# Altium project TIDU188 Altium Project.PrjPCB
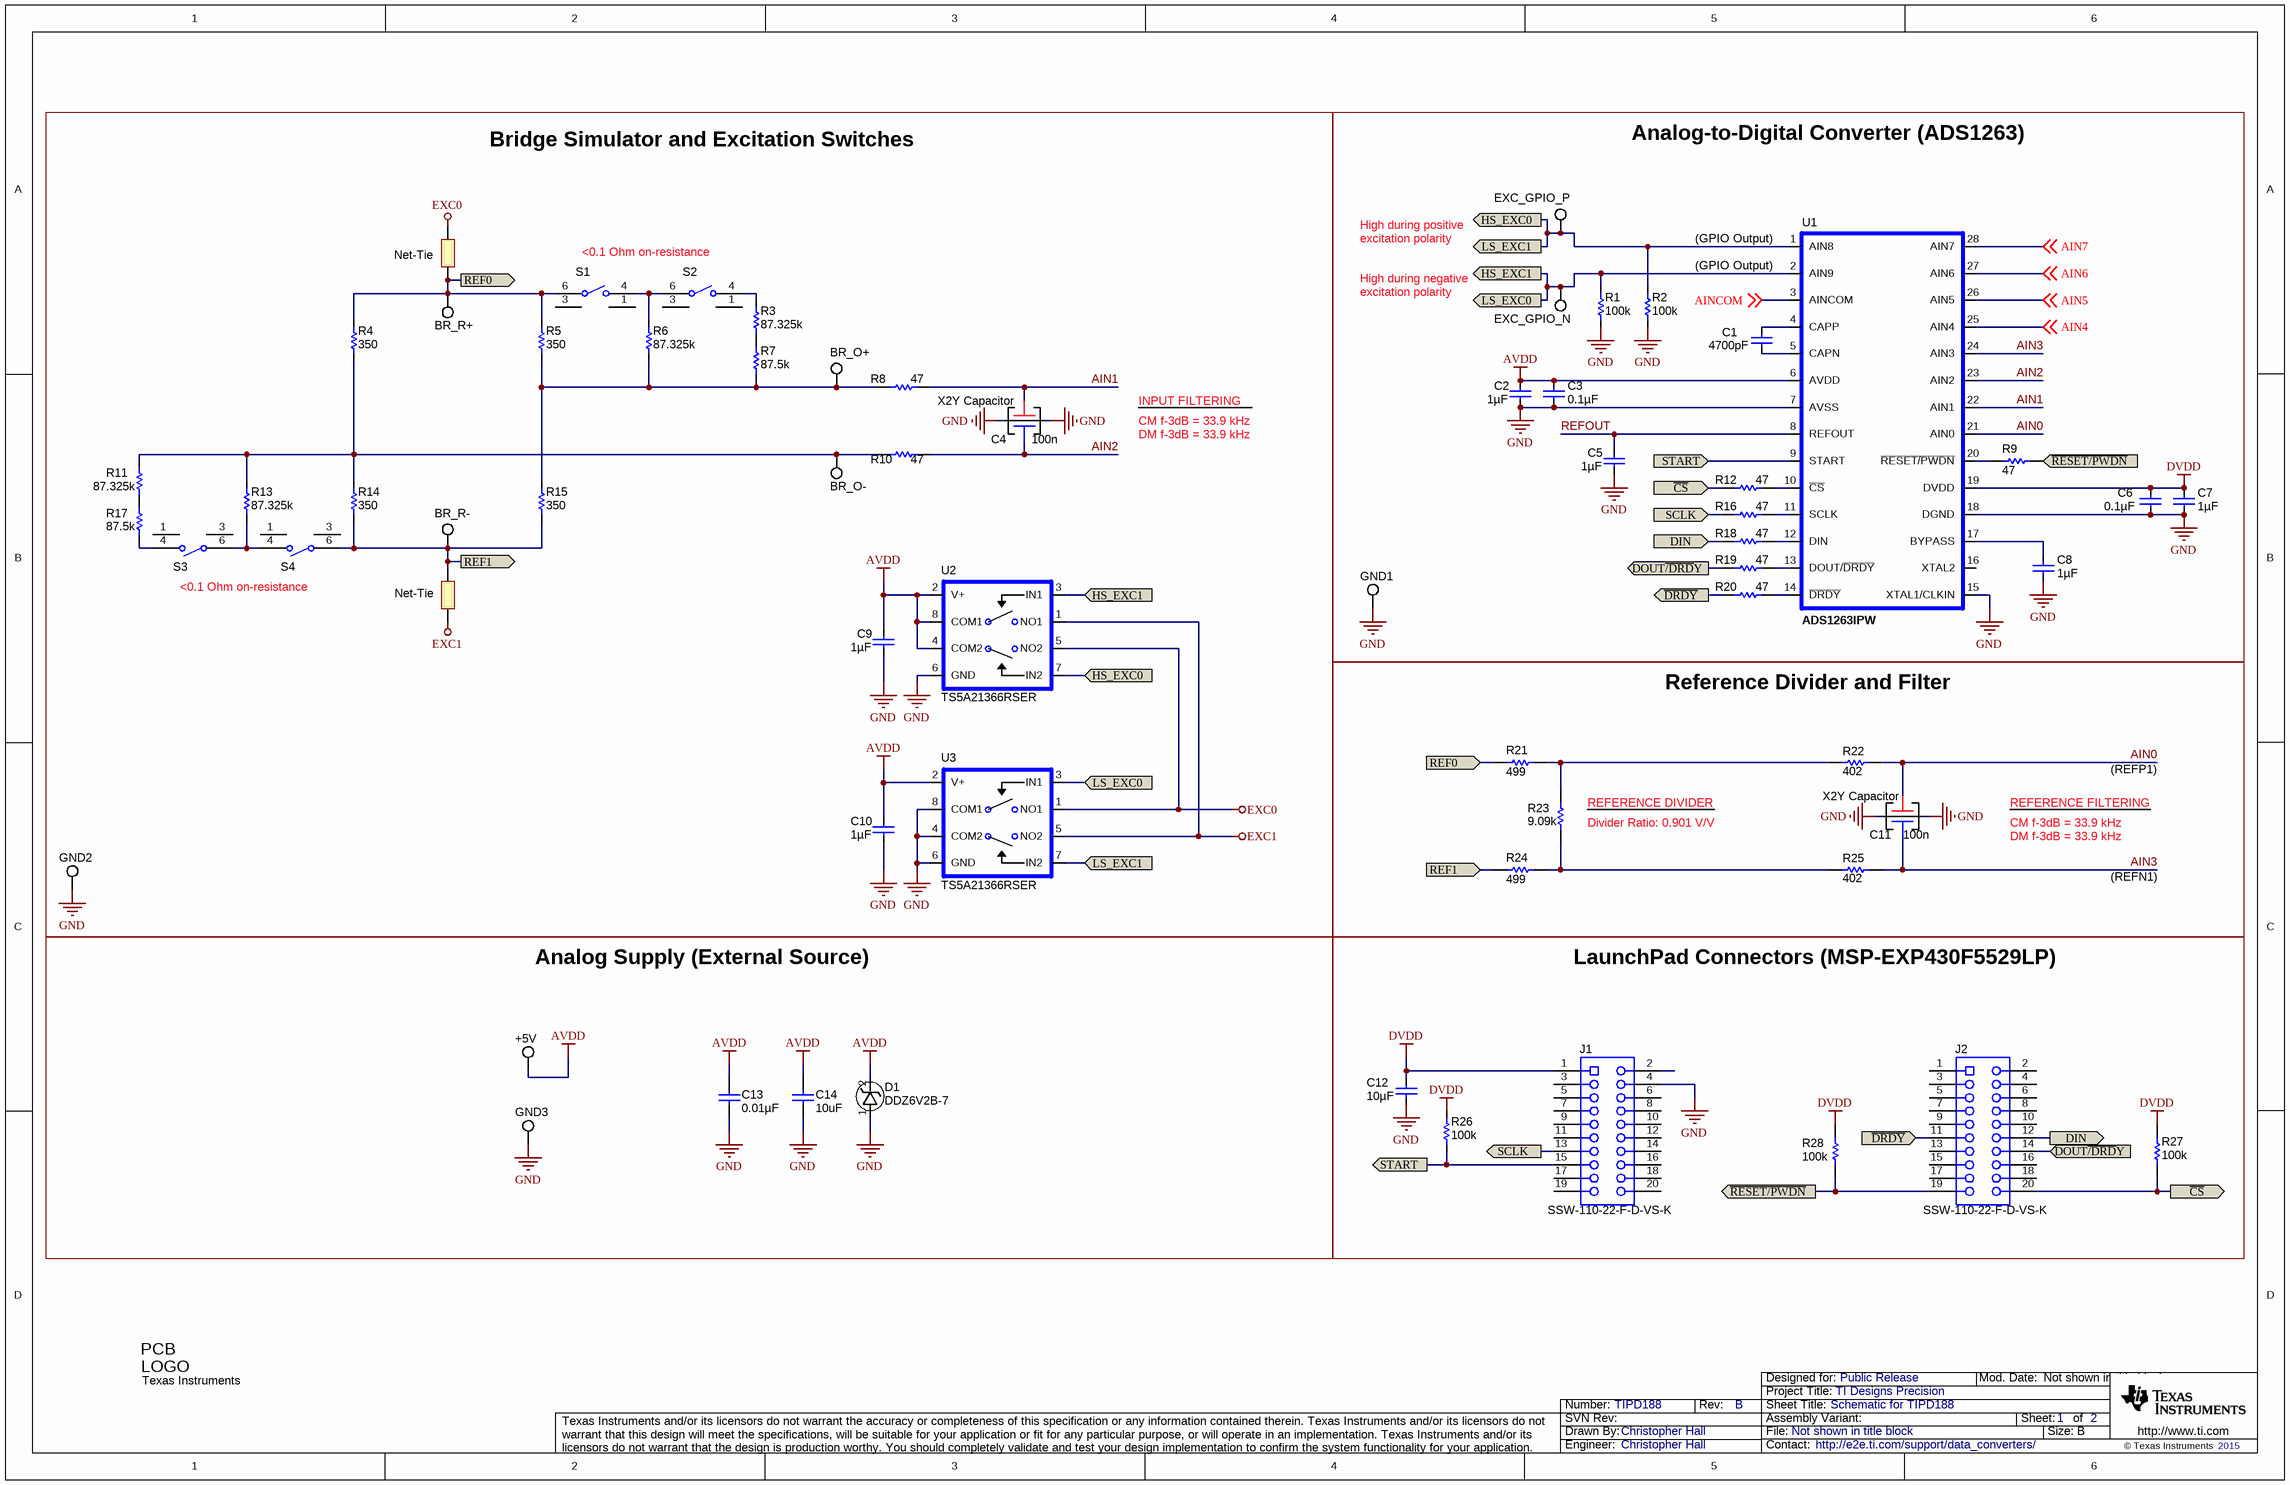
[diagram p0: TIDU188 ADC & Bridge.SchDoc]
CopyrightYear: 2015; EVM_Orderable: N/A; PCB_Layout: Robert Hoof; PCB_Rev: B; PRJ_Customer: Public Release; PRJ_Engineer: Christopher Hall; PRJ_Number: TIPD188; PRJ_Title: TI Designs Precision; SCH_Rev: B; TechSupport: http://e2e.ti.com/support/data_converters/; TID: TIPD188
2 sheets, 74 parts. Net scope: flat (ports and power ports of the same name join across sheets).
Board file: TIDU188 PCB Layout.PcbDoc
Sheets:
  TIDU188 ADC & Bridge.SchDoc
  TIDU188 Temp Sensor.SchDoc

## Sheet TIDU188 ADC & Bridge.SchDoc: Schematic for TIPD188
size 431 x 279 mm; Date: Not shown in title block; ApprovedBy: Not shown in title block; CheckedBy: Not shown in title block; Author: Not shown in title block; CompanyName: Not shown in title block; DrawnBy: Christopher Hall; Engineer: Not shown in title block; Organization: Not shown in title block; Address1: Not shown in title block; Address2: Not shown in title block; Address3: Not shown in title block; Address4: Not shown in title block; DocumentNumber: 1; Revision: Use project parameter SCH_Rev; SheetNumber: 1; SheetTotal: 2; PageSetup: Record=PageOptions¦CenterHorizontal=True¦CenterVertical=True¦PrintScale=1.00¦XCorrection=1.00¦YCorrection=1.00¦PrintKind=0¦BorderSize=5000000¦LeftOffset=0¦BottomOffset=0¦Orientation=2¦PaperLength=1000¦PaperWidth=1000¦Scale=100¦PaperSource=15¦PrintQuality=600¦MediaType=1¦DitherType=10¦PaperKind=Letter¦PrintScaleMode=1

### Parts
+5V  5015  [5015]  (value not drawn)
BR_O+  5015  [5015]  (value not drawn)
BR_O-  5015  [5015]  (value not drawn)
BR_R+  5015  [5015]  (value not drawn)
BR_R-  5015  [5015]  (value not drawn)
C1  value 4700pF  [0603]  (hidden comment: GRM188R71H472KA01D)
C2  value 1µF  [0603]  (hidden comment: GRM185R61C105KE44D)
C3  value 0.1µF  [0603]  (hidden comment: GRM188R71C104KA01D)
C4  value 100n  [X2Y 0805 (X15)]  (hidden comment: 250X15W104MV4E)
C5  value 1µF  [0603]  (hidden comment: GRM185R61C105KE44D)
C6  value 0.1µF  [0603]  (hidden comment: GRM188R71C104KA01D)
C7  value 1µF  [0603]  (hidden comment: GRM185R61C105KE44D)
C8  value 1µF  [0603]  (hidden comment: GRM185R61C105KE44D)
C9  value 1µF  [0603]  (hidden comment: GRM185R61C105KE44D)
C10  value 1µF  [0603]  (hidden comment: GRM185R61C105KE44D)
C11  value 100n  [X2Y 0805 (X15)]  (hidden comment: 250X15W104MV4E)
C12  value 10µF  [1206]  (hidden comment: C3216X7R1C106M)
C13  ValueDisplayed: 0.01µF  [0603]  (hidden comment: GRM188R71E103KA01D)
C14  value 10uF  [1206]  (hidden comment: C3216X7R1C106M)
D1  DDZ6V2B-7  [SOD-123]
EXC_GPIO_N  5015  [5015]  (value not drawn)
EXC_GPIO_P  5015  [5015]  (value not drawn)
GND1  5015  [5015]  (value not drawn)
GND2  5015  [5015]  (value not drawn)
GND3  5015  [5015]  (value not drawn)
J1  SSW-110-22-F-D-VS-K  [CONN_SSW-110-22-F-D-VS-K]
J2  SSW-110-22-F-D-VS-K  [CONN_SSW-110-22-F-D-VS-K]
Logo1  Texas Instruments  [TI_Horizontal_Overlay_Small]  (no BOM)
NT1  Net-Tie  [Net-Tie_10mil]  (net tie, no BOM)
NT2  Net-Tie  [Net-Tie_10mil]  (net tie, no BOM)
R1  value 100k  [0603]  (hidden comment: ERJ-3GEYJ104V)
R2  value 100k  [0603]  (hidden comment: ERJ-3GEYJ104V)
R3  value 87.325k  [2512]  (hidden comment: 804-2512)
R4  value 350  [1206]  (hidden comment: 804-1206)
R5  value 350  [1206]  (hidden comment: 804-1206)
R6  value 87.325k  [2512]  (hidden comment: 804-2512)
R7  value 87.5k  [2512]  (hidden comment: 804-2512)
R8  value 47  [0805_HV]  (hidden comment: ERJ-3EKF47R0V)
R9  value 47  [0603]  (hidden comment: ERJ-3EKF47R0V)
R10  value 47  [0805_HV]  (hidden comment: ERJ-3EKF47R0V)
R11  value 87.325k  [2512]  (hidden comment: 804-2512)
R12  value 47  [0603]  (hidden comment: ERJ-3EKF47R0V)
R13  value 87.325k  [2512]  (hidden comment: 804-2512)
R14  value 350  [1206]  (hidden comment: 804-1206)
R15  value 350  [1206]  (hidden comment: 804-1206)
R16  value 47  [0603]  (hidden comment: ERJ-3EKF47R0V)
R17  value 87.5k  [2512]  (hidden comment: 804-2512)
R18  value 47  [0603]  (hidden comment: ERJ-3EKF47R0V)
R19  value 47  [0603]  (hidden comment: ERJ-3EKF47R0V)
R20  value 47  [0603]  (hidden comment: ERJ-3EKF47R0V)
R21  value 499  [0603]  (hidden comment: RG1608P-4990-B-T5)
R22  value 402  [0805_HV]  (hidden comment: 2-1879336-4)
R23  value 9.09k  [0603]  (hidden comment: RG1608P-9091-B-T5)
R24  value 499  [0603]  (hidden comment: RG1608P-4990-B-T5)
R25  value 402  [0805_HV]  (hidden comment: 2-1879336-4)
R26  value 100k  [0603]  (hidden comment: ERJ-3GEYJ104V)
R27  value 100k  [0603]  (hidden comment: ERJ-3GEYJ104V)
R28  value 100k  [0603]  (hidden comment: ERJ-3GEYJ104V)
S1  200USP9T1A1M2RE  [200USP9xxxxM2]  (value not drawn)
S2  200USP9T1A1M2RE  [200USP9xxxxM2]  (value not drawn)
S3  200USP9T1A1M2RE  [200USP9xxxxM2]  (value not drawn)
S4  200USP9T1A1M2RE  [200USP9xxxxM2]  (value not drawn)
U1  ADS1263IPW  [PW28]
U2  TS5A21366RSER  [RSE-8]
U3  TS5A21366RSER  [RSE-8]

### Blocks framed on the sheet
Bridge Simulator and Excitation Switches: BR_O+ BR_O- BR_R+ BR_R- C4 C9 C10 GND2 NT1 NT2 R3-R8 R10 R11 R13-R15 R17 S1-S4 U2 U3
Analog-to-Digital Converter (ADS1263): C1-C3 C5-C8 EXC_GPIO_N EXC_GPIO_P GND1 R1 R2 R9 R12 R16 R18-R20 U1
Reference Divider and Filter: C11 R21-R25
Analog Supply (External Source): +5V C13 C14 D1 GND3
LaunchPad Connectors (MSP-EXP430F5529LP): C12 J1 J2 R26-R28

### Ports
DIN (in), DIN (out), DOUT~{/DRD}Y (in), DOUT~{/DRD}Y (out), HS_EXC0, HS_EXC1, LS_EXC0, LS_EXC1, REF0 (in), REF0 (out), REF1 (in), REF1 (out), SCLK (in), SCLK (out), START (in), START (out), ~{CS} (in), ~{CS} (out), ~{DRDY} (in), ~{DRDY} (out), ~{RESET/PWDN} (in), ~{RESET/PWDN} (out)

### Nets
AVDD: +5V.1 C2.1 C3.1 C9.2 C10.2 C13.1 C14.1 D1.2(Cathode) U1.6(AVDD) U2.2(V+) U2.4(COM2) U2.8(COM1) U3.2(V+)
DVDD: C6.1 C7.1 C12.1 J1.1 R26.1 R27.1 R28.2 U1.19(DVDD)
EXC0: NT1.2 U2.5(NO2) U3.1(NO1)
EXC1: NT2.1 U2.1(NO1) U3.5(NO2)
GND: C2.2 C3.2 C4.G C5.2 C6.2 C7.2 C8.2 C9.1 C10.1 C11.G C12.2 C13.2 C14.2 D1.1(Anode) GND1.1 GND2.1 GND3.1 J1.4 R1.2 R2.2 U1.7(AVSS) U1.15(XTAL1/CLKIN) U1.18(DGND) U2.6(GND) U3.4(COM2) U3.6(GND) U3.8(COM1)
~{CS}: J2.20 R12.2 R27.2 ; port ~{CS}
~{DRDY}: J2.11 R20.2 ; port ~{DRDY}
~{RESET/PWDN}: J2.19 R9.2 R28.1 ; port ~{RESET/PWDN}
AIN0: C11.A R22.2 U1.21(AIN0)
AIN1: C4.A R8.2 U1.22(AIN1)
AIN2: C4.B R10.2 U1.23(AIN2)
AIN3: C11.B R25.2 U1.24(AIN3)
AIN4: U1.25(AIN4) ; off-sheet AIN4
AIN5: U1.26(AIN5) ; off-sheet AIN5
AIN6: U1.27(AIN6) ; off-sheet AIN6
AIN7: U1.28(AIN7) ; off-sheet AIN7
AINCOM: U1.3(AINCOM) ; off-sheet AINCOM
DIN: J2.12 R18.2 ; port DIN
DOUT~{/DRD}Y: J2.14 R19.2 ; port DOUT~{/DRD}Y
HS_EXC0: EXC_GPIO_P.1 R2.1 U1.1(AIN8) U2.7(IN2) U3.7(IN2) ; port HS_EXC0, port LS_EXC1
HS_EXC1: EXC_GPIO_N.1 R1.1 U1.2(AIN9) U2.3(IN1) U3.3(IN1) ; port HS_EXC1, port LS_EXC0
REF0: BR_R+.1 NT1.1 R4.2 R5.2 R21.1 S1.6 ; port REF0
REF1: BR_R-.1 NT2.2 R14.1 R15.1 R24.1 S4.6 ; port REF1
REFOUT: C5.1 U1.8(REFOUT)
SCLK: J1.13 R16.2 ; port SCLK
START: J1.15 R26.2 U1.9(START) ; port START
NetBR_O+_1: BR_O+.1 R5.1 R6.1 R7.1 R8.1 R15.2
NetBR_O-_1: BR_O-.1 R4.1 R10.1 R11.2 R13.2 R14.2
NetC1_1: C1.1 U1.4(CAPP)
NetC1_2: C1.2 U1.5(CAPN)
NetC8_1: C8.1 U1.17(BYPASS)
NetR3_1: R3.1 R7.2
NetR3_2: R3.2 S2.4
NetR6_2: R6.2 S1.4 S2.6
NetR9_1: R9.1 U1.20(~{RESET/PWDN})
NetR11_1: R11.1 R17.2
NetR12_1: R12.1 U1.10(~{CS})
NetR13_1: R13.1 S3.6 S4.4
NetR16_1: R16.1 U1.11(SCLK)
NetR17_1: R17.1 S3.4
NetR18_1: R18.1 U1.12(DIN)
NetR19_1: R19.1 U1.13(DOUT/~{DRDY})
NetR20_1: R20.1 U1.14(~{DRDY})
NetR21_2: R21.2 R22.1 R23.2
NetR23_1: R23.1 R24.2 R25.1

Not connected (* = marked no-connect by the designer): J1 2 3 5 6 7 8 9 10 11 12 14 16 17 18 19 20; J2 1 2 3 4 5 6 7 8 9 10 13 15 16 17 18; S1 1 3; S2 1 3; S3 1 3; S4 1 3; U1 16(XTAL2)

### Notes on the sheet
- High during positive
- <0.1 Ohm on-resistance
- excitation polarity
- High during negative
- (near U1) (GPIO Output)
- (near C4) X2Y Capacitor
- CM f-3dB = 33.9 kHz
- DM f-3dB = 33.9 kHz
- INPUT FILTERING
- (REFP1)
- (near R23) Divider Ratio: 0.901 V/V
- (near R23) REFERENCE DIVIDER
- (near C11) X2Y Capacitor
- REFERENCE FILTERING
- (REFN1)

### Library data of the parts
+5V BR_O+ BR_O- BR_R+ BR_R- EXC_GPIO_N EXC_GPIO_P GND1-GND3 = Test Point SMT: TEST POINT, MINIATURE, SMT; Manufacturer: Keystone Electronics; SymbolCreator: a0282860; U/M: EA
C1 = Cap_small: CAP, CERM, 4700pF, 50V, +/-10%, X7R, 0603; Manufacturer: MuRata; SymbolCreator: a0282860; CompType: Capacitor; U/M: EA
C2 C5 C7-C10 = Cap_small: CAP, CERM, 1uF, 16V, +/-10%, X5R, 0603; Manufacturer: MuRata; SymbolCreator: a0282860; CompType: Capacitor; U/M: EA
C3 C6 = Cap_small: CAP, CERM, 0.1uF, 16V, +/-10%, X7R, 0603; Manufacturer: MuRata; SymbolCreator: a0282860; CompType: Capacitor; U/M: EA
C4 C11 = CAP_X2Y: CAP, CERM X2Y, 100 nF, 25V, X7R, +/-20%, 0805; Manufacturer: Johanson Dielectrics Inc; SymbolCreator: a0282860; U/M: EA; CompType: X2Y Capacitor
C12 = Cap_small: CAP, CERM, 10 uF, 16V, X7R +/-20%, 1206; Manufacturer: TDK; PartNumber: C3216X7R1C106M160AC; SymbolCreator: a0282860; CompType: Capacitor; U/M: EA
C13 = GRM188R71E103KA01D: CAP, CERM, 0.01uF, 25V, +/-10%, X7R, 0603; Manufacturer: MuRata; Polarized: N; CompType: Capacitor; U/M: EA; Cap_F: 0.00000001; Tolerance_%: 10; Value1: Unknown; VDC_V: 25; TaMin_C: -55; TaMax_C: 125
C14 = Capacitor: CAP, CERM, 10 uF, 16V,  X7R +/-20%, 1206; Manufacturer: TDK; Polarized: N; U/M: EA; SymbolCreator: a0282860; Tolerance: 20%
D1 = Zener Diode: DIODE, ZENER, 6.2V, 500mW, SOD-123; Manufacturer: Diodes Inc; SymbolCreator: a0282860; U/M: EA
J1 J2 = SSW-110-22-F-D-VS-K: Connector, Receptacle, 100mil, 10x2, Gold plated, SMD; Manufacturer: Samtec; SymbolCreator: a0412235; U/M: EA
Logo1 = TI_Logo: Texas Instrument Corporate Signature; SymbolCreator: a0412235
NT1 NT2 = Net-Tie: Single point connection between nets.; SymbolCreator: codlsc
R1 R2 R26 = Resistor_small: RES, 100k Ohm, 5%, 1/10W, 0603; Manufacturer: Panasonic; U/M: EA
R3 R6 R11 R13 = Resistor_small: RES, 87.325k Ohm, 0.01%, 0.75W, 2512; Manufacturer: Vishay; U/M: EA
R4 R5 R14 R15 = Resistor_small: RES, 350 Ohm, 0.25%, 0.3W, 1206; Manufacturer: Vishay; U/M: EA
R7 = Resistor_small: RES, 87.5 kohm, 0.5%, 0.75W, 2512; Manufacturer: Vishay; U/M: EA
R8-R10 R12 R16 R18-R20 = Resistor: RES, 47 Ohm, 1%, 1/10W, 0603; Manufacturer: Panasonic; U/M: EA; SymbolCreator: a0282860
R17 = Resistor_small: RES, 87.5k Ohm, 0.5%, 0.75W, 2512; Manufacturer: Vishay; U/M: EA
R21 R24 = RG1608P-4990-B-T5: RES, 499 ohm, 0.1%, 0.1W, 0603; Manufacturer: Susumu Co Ltd; CompType: Resistor; Value_Code: 499R; Tolerance_%: 0.1; VDC_V: 75; TempCo: 25 ppm/C; EIA_Code: E192; U/M: EA
R22 R25 = Resistor: RES, 47 Ohm, 1%, 1/10W, 0603; Manufacturer: TE Connectivity AMP Connectors; Power_W: 0.063W, 1/16W; TempCo: ±50ppm/°C
R23 = RG1608P-9091-B-T5: RES, 9.09k ohm, 0.1%, 0.1W, 0603; Manufacturer: Susumu Co Ltd; CompType: Resistor; Res_ohm: 9090; Value_Code: 9k09; Tolerance_%: 0.1; VDC_V: 75; TempCo: 25 ppm/C; EIA_Code: E192; U/M: EA
R27 R28 = Resistor: RES, 100k Ohm, 5%, 1/10W, 0603; Manufacturer: Panasonic; U/M: EA; SymbolCreator: a0282860
S1-S4 = 200USP9T1A1M2RE: Switch, Toggle, SPST, 1Pos, TH; Manufacturer: E-Switch; SymbolCreator: a0411947; VDC_V: 20; SwitchFunction: Off-On; PositionCount: 1; CurrentRating_mA: 400
U1 = ADS126XPW: IC, 32-bit, 38kSPS ADC; MFR: TI; Second Source: C:\program files\p-cad 2004\pcad_pdf's\ADS1262_Pinout.doc; Reference: \\vette02\pmp_pcb\pcad_pdf's\ADS1262_Pinout.doc; Area: 85.53 mm
U2 U3 = TS5A21366RSE: IC, Single-Channel 10 Ohms SPDT Analog Switch with enable; Manufacturer: TI; Alternate Manufacturer: None; Area: 6.25 mm

## Sheet TIDU188 Temp Sensor.SchDoc: Schematic for TIPD188 (Not Used)
size 431 x 279 mm; Date: Not shown in title block; ApprovedBy: Not shown in title block; CheckedBy: Not shown in title block; Author: Not shown in title block; CompanyName: Not shown in title block; DrawnBy: Christopher Hall; Engineer: Christopher Hall; Organization: Not shown in title block; Address1: Not shown in title block; Address2: Not shown in title block; Address3: Not shown in title block; Address4: Not shown in title block; DocumentNumber: 1; Revision: Use project parameter SCH_Rev; SheetNumber: 2; SheetTotal: 2; PageSetup: Record=PageOptions¦CenterHorizontal=True¦CenterVertical=True¦PrintScale=1.00¦XCorrection=1.00¦YCorrection=1.00¦PrintKind=0¦BorderSize=5000000¦LeftOffset=0¦BottomOffset=0¦Orientation=2¦PaperLength=1000¦PaperWidth=1000¦Scale=100¦PaperSource=15¦PrintQuality=600¦MediaType=1¦DitherType=10¦PaperKind=Letter¦PrintScaleMode=1
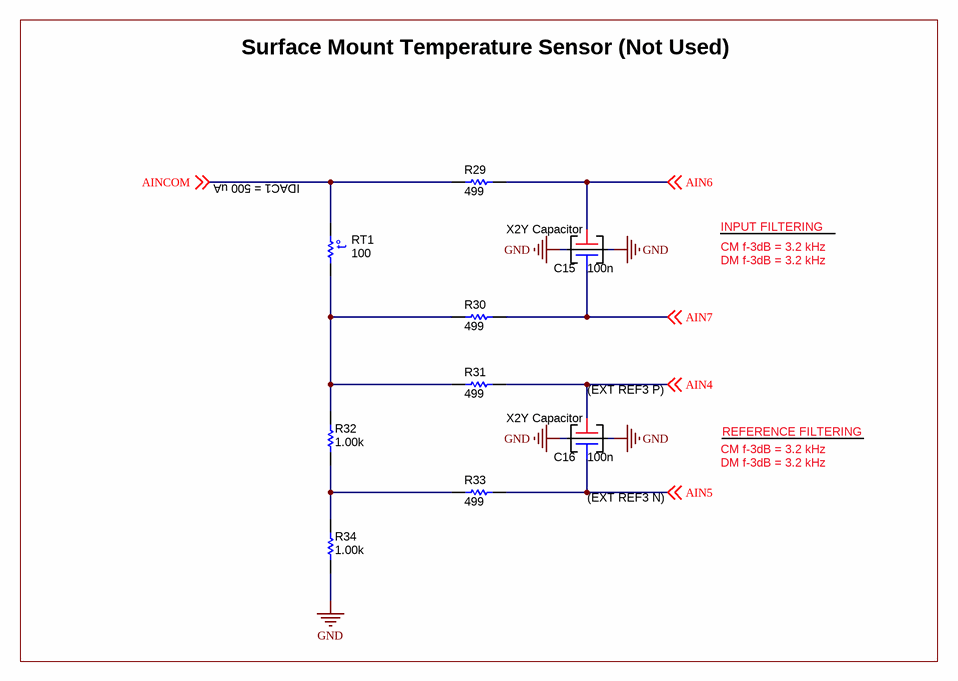
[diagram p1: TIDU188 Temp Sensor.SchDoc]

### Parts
C15  value 100n  [X2Y 0805 (X15)]  (hidden comment: 250X15W104MV4E)
C16  value 100n  [X2Y 0805 (X15)]  (hidden comment: 250X15W104MV4E)
R29  value 499  [0603]  (hidden comment: RC0603FR-07499RL)
R30  value 499  [0603]  (hidden comment: RC0603FR-07499RL)
R31  value 499  [0603]  (hidden comment: RC0603FR-07499RL)
R32  value 1.00k  [0805_HV]  (hidden comment: RG2012P-102-B-T5)
R33  value 499  [0603]  (hidden comment: RC0603FR-07499RL)
R34  value 1.00k  [0805_HV]  (hidden comment: RG2012P-102-B-T5)
RT1  value 100  [1206]  (hidden comment: PTS120601B100RP100)

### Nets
GND: C15.G C16.G R34.1
AIN4: C16.A R31.2 ; off-sheet AIN4
AIN5: C16.B R33.2 ; off-sheet AIN5
AIN6: C15.A R29.2 ; off-sheet AIN6
AIN7: C15.B R30.2 ; off-sheet AIN7
AINCOM: R29.1 RT1.2 ; off-sheet AINCOM
NetR30_1: R30.1 R31.1 R32.2 RT1.1
NetR32_1: R32.1 R33.1 R34.2

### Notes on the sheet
- Surface Mount Temperature Sensor (Not Used)
- (near RT1) IDAC1 = 500 uA
- (near C15) X2Y Capacitor
- CM f-3dB = 3.2 kHz
- INPUT FILTERING
- DM f-3dB = 3.2 kHz
- (near C16) X2Y Capacitor
- (near C16) (EXT REF3 P)
- REFERENCE FILTERING
- (near C16) (EXT REF3 N)

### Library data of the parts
C15 C16 = CAP_X2Y: as C4 on sheet TIDU188 ADC & Bridge
R29-R31 R33 = RC0603FR-07499RL: RES, 499 ohm, 1%, 0.1W, 0603; Manufacturer: Yageo America; CompType: Resistor; Value_Code: 499R; Tolerance_%: 1; Power_W: 0.1; VDC_V: 150; TempCo: 200 ppm/C; EIA_Code: E96; U/M: EA
R32 R34 = RG2012P-102-B-T5: RES, 1.00k ohm, 0.1%, 0.125W, 0805; Manufacturer: Susumu Co Ltd; CompType: Resistor; Res_ohm: 1000; Value_Code: 1k00; Tolerance_%: 0.1; Power_W: 0.125; VDC_V: 100; TempCo: 25 ppm/C; EIA_Code: E192; U/M: EA
RT1 = PTS120601B100RP100: Temperature Sensor, 100 ohm, 1%, 1206; Manufacturer: Vishay/Beyschlag; CompType: Temp Sensor

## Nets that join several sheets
GND: TIDU188 ADC & Bridge (27 pins), TIDU188 Temp Sensor (C15.G C16.G R34.1)
AIN4: TIDU188 ADC & Bridge (U1.25), TIDU188 Temp Sensor (C16.A R31.2)
AIN5: TIDU188 ADC & Bridge (U1.26), TIDU188 Temp Sensor (C16.B R33.2)
AIN6: TIDU188 ADC & Bridge (U1.27), TIDU188 Temp Sensor (C15.A R29.2)
AIN7: TIDU188 ADC & Bridge (U1.28), TIDU188 Temp Sensor (C15.B R30.2)
AINCOM: TIDU188 ADC & Bridge (U1.3), TIDU188 Temp Sensor (R29.1 RT1.2)

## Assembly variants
001: all parts fitted
002: not fitted C15 C16 R3 R7 R11 R17 R23 R29 R30 R31 R32 R33 R34 RT1 S2 S3; alternate parts R21 -> MCR03EZPJ000, R24 -> MCR03EZPJ000, R22 -> MCR03EZPJ000, R25 -> MCR03EZPJ000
